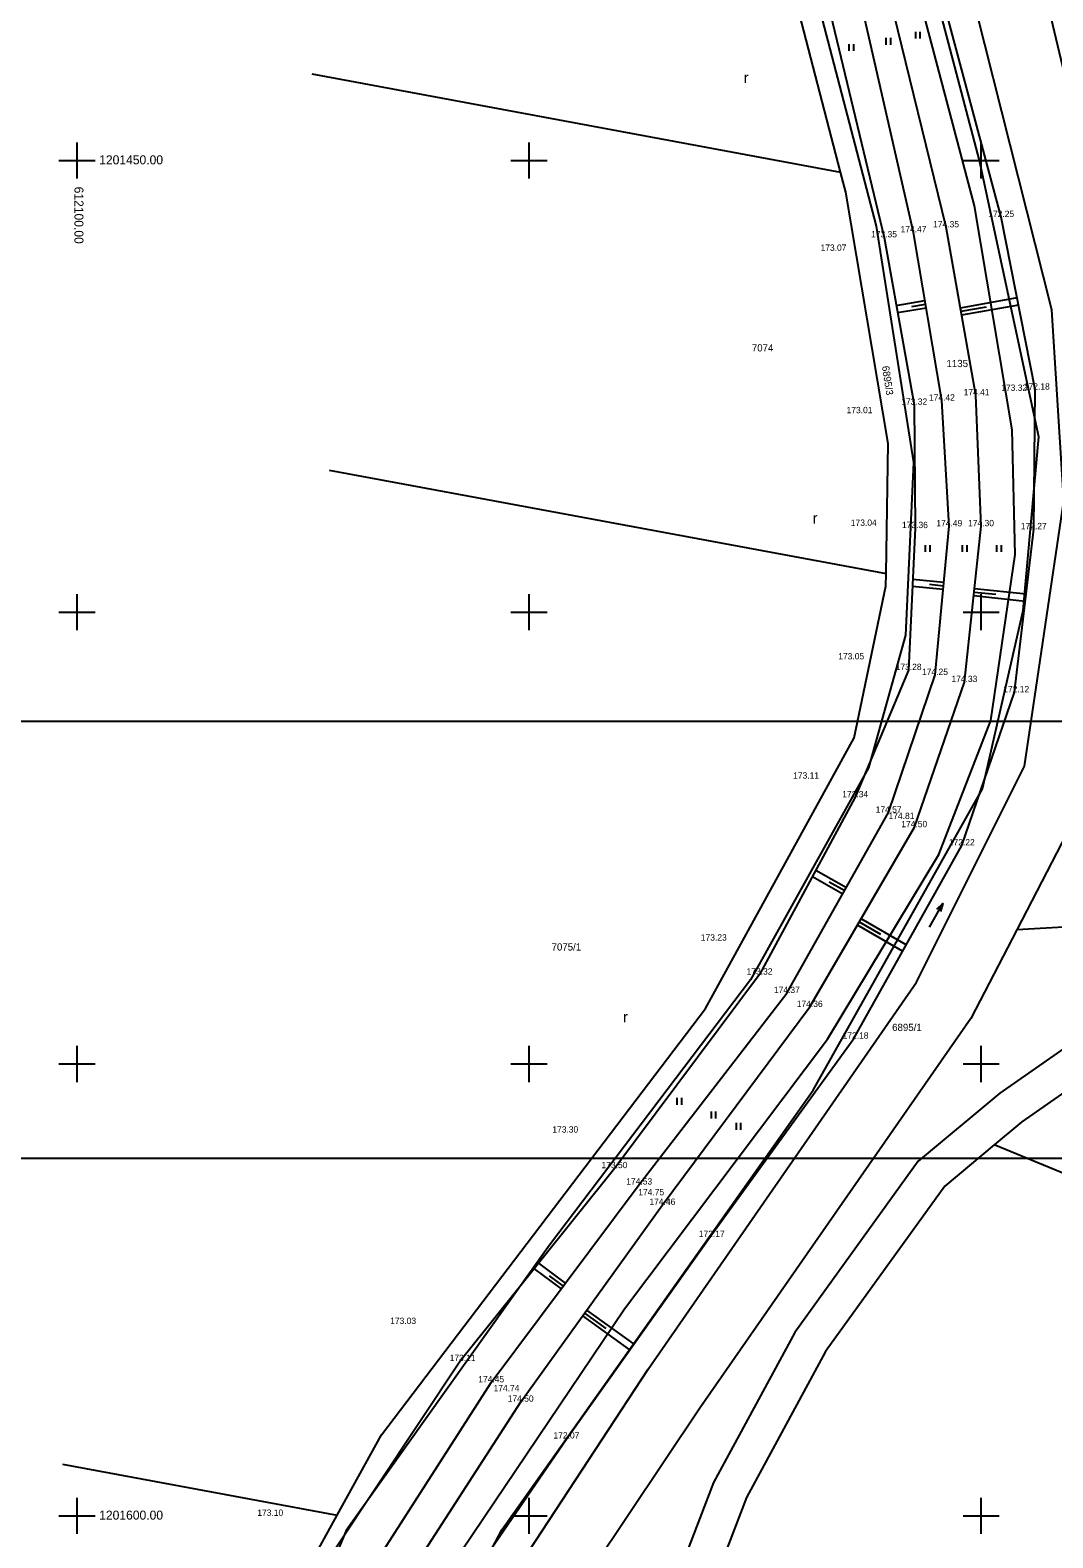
# Model space of a CAD drawing. Extents: x -612546 to -611926, y -1201932 to -1200444.
# Drawn here: x -612105.2 to -611992.1, y -1201602.4 to -1201435.6 of the extents above; entities that cross this region are included whole.
import ezdxf

# ---------------------------------------------------------------- set-up
doc = ezdxf.new("R2010")
doc.units = 0
for name, color, linetype in [('14 hrana pata svahu', 7, 'Continuous'), ('15 šrafy', 7, 'Continuous'), ('61 legenda křížky', 7, 'Continuous'), ('Hranice parcel', 7, 'Continuous'), ('Parcelní čísla', 7, 'Continuous'), ('Vnitřní kresba', 7, 'Continuous'), ('Vrstva 36', 7, 'Continuous'), ('Vrstva 45', 7, 'Continuous'), ('Vrstva 63', 7, 'Continuous'), ('výška bodu', 7, 'Continuous')]:
    doc.layers.add(name, color=color, linetype=linetype)

msp = doc.modelspace()

# ---------------------------------------------------------------- linework, layer by layer
at = {"layer": '14 hrana pata svahu'}
for points in [[(-612064.14, -1201607.91), (-612050.9, -1201587.38), (-612035.24, -1201565.59), (-612018.94, -1201543.69), (-612007.37, -1201523.79), (-612001.85, -1201507.73), (-611999.98, -1201490.48), (-612000.59, -1201475.99), (-612003.88, -1201457.4), (-612010.08, -1201431.88), (-612017.13, -1201405.07), (-612023.96, -1201380.26), (-612030.88, -1201354.05), (-612037.79, -1201327.9), (-612045.18, -1201301.85), (-612055.08, -1201267.97)], [(-612058.46, -1201609.91), (-612045.84, -1201591.45), (-612030, -1201569.15), (-612014.09, -1201547.19), (-612002.14, -1201525.81), (-611996.32, -1201508.86), (-611994.18, -1201490.81), (-611994.04, -1201475.36), (-611997.78, -1201456.26), (-612004.46, -1201431.28), (-612011.71, -1201404.48), (-612018.59, -1201378.49), (-612025.7, -1201352.72), (-612032.15, -1201326.28), (-612039.66, -1201300.7), (-612048.13, -1201268.75)], [(-612067.33, -1201605.71), (-612054.19, -1201585.24), (-612037.82, -1201563.34), (-612021.49, -1201542.15), (-612010.23, -1201522.18), (-612005.1, -1201506.94), (-612003.52, -1201490.49), (-612004.34, -1201476.58), (-612007.48, -1201457.96), (-612013.23, -1201432.72), (-612020.3, -1201406.08), (-612027.21, -1201381.29), (-612034.3, -1201355.08), (-612041.2, -1201328.91), (-612048.01, -1201302.49), (-612056.96, -1201270.5)], [(-612072.85, -1201271.87), (-612059.61, -1201273.55), (-612051.46, -1201303.54), (-612044.5, -1201329.67), (-612037.67, -1201355.97), (-612030.48, -1201382.34), (-612024.02, -1201407.2), (-612016.67, -1201433.81), (-612010.74, -1201458.51), (-612007.4, -1201477.04), (-612007.3, -1201490.69), (-612008.02, -1201506.4), (-612013.93, -1201520.48), (-612024.51, -1201540.1), (-612040.53, -1201561.53), (-612057.63, -1201582.88), (-612071.39, -1201603.6)]]:
    msp.add_lwpolyline(points, dxfattribs=at)
at = {"layer": '15 šrafy'}
for p, q in [((-612009.38, -1201466.04), (-612006.21, -1201465.51)), ((-612007.67, -1201466.16), (-612006.14, -1201465.9)), ((-611996.03, -1201465.22), (-612002.3, -1201466.33)), ((-612009.24, -1201466.83), (-612006.07, -1201466.3)), ((-611999.43, -1201466.23), (-612002.23, -1201466.73)), ((-611995.87, -1201466.01), (-612002.16, -1201467.12)), ((-612007.6, -1201497.13), (-612004.19, -1201497.46)), ((-612007.56, -1201496.33), (-612004.11, -1201496.66)), ((-612005.71, -1201496.91), (-612004.15, -1201497.06)), ((-611995.03, -1201498.01), (-612000.73, -1201497.4)), ((-611995.13, -1201498.81), (-612000.82, -1201498.19)), ((-611998.38, -1201498.05), (-612000.77, -1201497.8)), ((-612018.66, -1201529.25), (-612015.29, -1201531.15)), ((-612018.28, -1201528.55), (-612014.9, -1201530.46)), ((-612016.8, -1201529.84), (-612015.09, -1201530.81)), ((-612011.09, -1201535.67), (-612013.47, -1201534.29)), ((-612008.3, -1201536.83), (-612013.27, -1201533.94)), ((-612008.69, -1201537.53), (-612013.67, -1201534.63)), ((-612049.45, -1201572.67), (-612046.46, -1201574.9)), ((-612048.95, -1201572.05), (-612045.99, -1201574.26)), ((-612047.76, -1201573.44), (-612046.22, -1201574.58)), ((-612041.47, -1201579.26), (-612043.84, -1201577.56)), ((-612038.4, -1201580.97), (-612043.61, -1201577.23)), ((-612038.86, -1201581.63), (-612044.07, -1201577.88))]:
    msp.add_line(p, q, dxfattribs=at)
at = {"layer": '61 legenda křížky'}
for p, q in [((-612100, -1201452), (-612100, -1201448)), ((-612050, -1201452), (-612050, -1201448)), ((-612000, -1201452), (-612000, -1201448)), ((-612102, -1201450), (-612098, -1201450)), ((-612052, -1201450), (-612048, -1201450)), ((-612002, -1201450), (-611998, -1201450)), ((-612100, -1201502), (-612100, -1201498)), ((-612050, -1201502), (-612050, -1201498)), ((-612000, -1201502), (-612000, -1201498)), ((-612102, -1201500), (-612098, -1201500)), ((-612052, -1201500), (-612048, -1201500)), ((-612002, -1201500), (-611998, -1201500)), ((-612100, -1201552), (-612100, -1201548)), ((-612050, -1201552), (-612050, -1201548)), ((-612000, -1201552), (-612000, -1201548)), ((-612102, -1201550), (-612098, -1201550)), ((-612052, -1201550), (-612048, -1201550)), ((-612002, -1201550), (-611998, -1201550)), ((-612100, -1201602), (-612100, -1201598)), ((-612050, -1201602), (-612050, -1201598)), ((-612000, -1201602), (-612000, -1201598)), ((-612102, -1201600), (-612098, -1201600)), ((-612052, -1201600), (-612048, -1201600)), ((-612002, -1201600), (-611998, -1201600))]:
    msp.add_line(p, q, dxfattribs=at)
at = {"layer": 'Hranice parcel'}
for p, q in [((-612015.54, -1201451.28), (-612029.85, -1201396.29)), ((-611969.89, -1201533.65), (-611996.06, -1201535.15)), ((-611949.12, -1201579.28), (-611998.56, -1201558.96))]:
    msp.add_line(p, q, dxfattribs=at)
for points in [[(-612177.46, -1201854.09), (-612171.97, -1201847.65), (-612125.97, -1201786.38), (-612109.19, -1201764.04), (-612092.57, -1201737.14), (-612080.39, -1201714.9), (-612074.78, -1201703.41), (-612071.98, -1201691.65), (-612072.2, -1201658.35), (-612070, -1201637.27), (-612065.73, -1201619.85), (-612059.82, -1201607.37), (-612039.46, -1201577.1), (-612017, -1201547.24), (-612004.68, -1201526.81), (-611998.92, -1201511.99), (-611996.24, -1201493.62), (-611996.58, -1201479.8), (-612000.74, -1201455.02), (-612027.1, -1201355.18), (-612050.25, -1201267.11)], [(-612060.22, -1201274.37), (-612037.81, -1201356.84), (-612011.62, -1201457.28), (-612007.48, -1201483.41), (-612008.37, -1201502.54), (-612012.46, -1201517.21), (-612025.5, -1201540.7), (-612047.75, -1201570.04), (-612070.24, -1201601.65), (-612078.31, -1201621), (-612081.97, -1201637.65), (-612083.96, -1201662.29), (-612084.12, -1201685.12), (-612084.75, -1201695.31), (-612087.47, -1201703.35), (-612103.05, -1201731.95), (-612118.98, -1201757.79), (-612136.57, -1201780.34), (-612179.16, -1201837.25), (-612189.22, -1201833.81)], [(-612009.76, -1201369.19), (-611997.24, -1201413.36), (-611984.77, -1201465.78), (-611983.62, -1201488.16), (-611987.79, -1201519.18), (-611996.06, -1201535.15)], [(-612074.03, -1201440.4), (-612015.54, -1201451.28)], [(-612010.52, -1201495.71), (-612010.29, -1201481.32), (-612014.96, -1201453.49), (-612015.54, -1201451.28)], [(-611964.05, -1201475.97), (-611960.2, -1201490.55), (-611957.25, -1201508.03), (-611957.35, -1201519.46), (-611960.34, -1201531.68), (-611967.57, -1201536.91), (-611995.49, -1201556.41), (-611998.56, -1201558.96)], [(-612072.1, -1201484.26), (-612010.52, -1201495.71)], [(-612071.21, -1201599.94), (-612066.31, -1201591.05), (-612030.5, -1201543.86), (-612014.06, -1201513.9), (-612010.54, -1201497.12), (-612010.52, -1201495.71)], [(-611969.89, -1201533.65), (-611997.92, -1201553.23), (-612006.98, -1201560.76), (-612020.6, -1201579.7), (-612029.6, -1201596.32), (-612036.2, -1201613.55), (-612042.99, -1201636.89), (-612045.15, -1201648.68)], [(-611996.06, -1201535.15), (-612001.15, -1201544.98), (-612031.12, -1201588.08), (-612050.83, -1201617.6), (-612058.05, -1201640.39)], [(-611998.56, -1201558.96), (-612004.03, -1201563.51), (-612017.2, -1201581.83), (-612025.96, -1201597.99), (-612032.41, -1201614.83), (-612039.09, -1201637.81), (-612039.19, -1201638.35)], [(-612101.6, -1201594.29), (-612071.21, -1201599.94)], [(-612086.09, -1201665.74), (-612083.97, -1201635.12), (-612078.56, -1201613.28), (-612071.21, -1201599.94)]]:
    msp.add_lwpolyline(points, dxfattribs=at)
at = {"layer": 'Vnitřní kresba'}
for points in [[(-612170.38, -1201848.81), (-612152.03, -1201823.55), (-612114.84, -1201773.75), (-612096.57, -1201746.92), (-612078.95, -1201716.04), (-612070.37, -1201697.01), (-612068.25, -1201638.15), (-612062.56, -1201619.7), (-612053.03, -1201601.55), (-612018.56, -1201552.89), (-611999.85, -1201519.56), (-611995.35, -1201499.82), (-611993.63, -1201480.57), (-612000.19, -1201450.02), (-612024.45, -1201357.81), (-612050.25, -1201267.11)], [(-612167.45, -1201850.95), (-612159.31, -1201839.87), (-612135.2, -1201807.83), (-612099.97, -1201758.55), (-612082.71, -1201730.21), (-612068.43, -1201702.85), (-612066.16, -1201687.46), (-612066.16, -1201656.85), (-612064.63, -1201639.3), (-612057.32, -1201615.06), (-612036.83, -1201583.77), (-612007.13, -1201540.95), (-611995.21, -1201517.05), (-611990.85, -1201487.68), (-611992.18, -1201466.53), (-612005.11, -1201415.22), (-612025.88, -1201339.7), (-612042.61, -1201277.13), (-612043.67, -1201266.17)]]:
    msp.add_lwpolyline(points, dxfattribs=at)
at = {"layer": 'Vrstva 36'}
for p, q in [((-612007.23, -1201436.51), (-612007.23, -1201435.76)), ((-612006.73, -1201436.51), (-612006.73, -1201435.76)), ((-612014.58, -1201437.86), (-612014.58, -1201437.11)), ((-612014.08, -1201437.86), (-612014.08, -1201437.11)), ((-612010.5, -1201437.19), (-612010.5, -1201436.44)), ((-612010, -1201437.19), (-612010, -1201436.44)), ((-612006.14, -1201493.31), (-612006.14, -1201492.56)), ((-612005.64, -1201493.31), (-612005.64, -1201492.56)), ((-612002.06, -1201493.31), (-612002.06, -1201492.56)), ((-612001.56, -1201493.31), (-612001.56, -1201492.56)), ((-611998.26, -1201493.31), (-611998.26, -1201492.56)), ((-611997.76, -1201493.31), (-611997.76, -1201492.56)), ((-612033.62, -1201554.51), (-612033.62, -1201553.76)), ((-612033.12, -1201554.51), (-612033.12, -1201553.76)), ((-612029.84, -1201556.02), (-612029.84, -1201555.27)), ((-612029.34, -1201556.02), (-612029.34, -1201555.27)), ((-612027.06, -1201557.28), (-612027.06, -1201556.53)), ((-612026.56, -1201557.28), (-612026.56, -1201556.53))]:
    msp.add_line(p, q, dxfattribs=at)
at = {"layer": 'Vrstva 45'}
msp.add_line((-612005.72, -1201534.85), (-612004.25, -1201532.23), dxfattribs=at)
msp.add_lwpolyline([(-612004.88, -1201532.88), (-612004.25, -1201532.23), (-612004.48, -1201533.11)], dxfattribs=at)
at = {"layer": 'Vrstva 63'}
for p, q in [((-612244.2, -1201512.06), (-611947.2, -1201512.06)), ((-611925.92, -1201560.45), (-612222.92, -1201560.45))]:
    msp.add_line(p, q, dxfattribs=at)

# ---------------------------------------------------------------- texts
at = {"layer": '61 legenda křížky'}
for s, p in [('1201450.00', (-612097.55, -1201450.43)), ('1201600.00', (-612097.55, -1201600.43))]:
    msp.add_text(s, height=1, dxfattribs=at).set_placement(p)
msp.add_text('612100.00', height=1, rotation=270, dxfattribs=at).set_placement((-612100.29, -1201452.9))
at = {"layer": 'Parcelní čísla'}
for s, p in [('7074', (-612025.36, -1201471.14)), ('1135', (-612003.83, -1201472.87)), ('7075/1', (-612047.51, -1201537.44)), ('6895/1', (-612009.84, -1201546.35))]:
    msp.add_text(s, height=0.8, dxfattribs=at).set_placement(p)
msp.add_text('6895/3', height=0.8, rotation=278.5677, dxfattribs=at).set_placement((-612010.97, -1201472.79))
at = {"layer": 'Vrstva 36'}
for p in [(-612026.26, -1201441.44), (-612018.63, -1201490.19), (-612039.6, -1201545.4)]:
    msp.add_text('r', height=1.2, dxfattribs=at).set_placement(p)
at = {"layer": 'výška bodu'}
for s, p in [('172.25', (-611999.21, -1201456.26)), ('174.47', (-612008.91, -1201457.96)), ('174.35', (-612005.31, -1201457.4)), ('173.35', (-612012.17, -1201458.51)), ('173.07', (-612017.76, -1201460)), ('174.42', (-612005.77, -1201476.58)), ('174.41', (-612001.93, -1201475.99)), ('173.32', (-611997.77, -1201475.5)), ('172.18', (-611995.27, -1201475.36)), ('173.01', (-612014.88, -1201477.97)), ('173.32', (-612008.83, -1201477.04)), ('173.04', (-612014.41, -1201490.44)), ('173.36', (-612008.75, -1201490.69)), ('174.49', (-612004.95, -1201490.49)), ('174.30', (-612001.44, -1201490.48)), ('172.27', (-611995.61, -1201490.81)), ('173.05', (-612015.8, -1201505.22)), ('173.28', (-612009.45, -1201506.4)), ('174.25', (-612006.53, -1201506.94)), ('174.33', (-612003.28, -1201507.73)), ('172.12', (-611997.55, -1201508.86)), ('173.11', (-612020.79, -1201518.41)), ('173.34', (-612015.36, -1201520.48)), ('174.57', (-612011.66, -1201522.18)), ('174.81', (-612010.24, -1201522.89)), ('174.50', (-612008.83, -1201523.79)), ('172.22', (-612003.57, -1201525.81)), ('173.23', (-612031, -1201536.34)), ('173.32', (-612025.94, -1201540.1)), ('174.37', (-612022.92, -1201542.15)), ('174.36', (-612020.39, -1201543.69)), ('172.18', (-612015.32, -1201547.19)), ('173.30', (-612047.43, -1201557.59)), ('173.50', (-612041.99, -1201561.53)), ('174.53', (-612039.25, -1201563.34)), ('174.75', (-612037.92, -1201564.53)), ('174.46', (-612036.69, -1201565.59)), ('172.17', (-612031.23, -1201569.15)), ('173.03', (-612065.36, -1201578.77)), ('173.11', (-612058.78, -1201582.88)), ('174.45', (-612055.62, -1201585.24)), ('174.74', (-612053.93, -1201586.22)), ('174.50', (-612052.36, -1201587.38)), ('172.07', (-612047.3, -1201591.45)), ('173.10', (-612080.06, -1201600.01))]:
    msp.add_text(s, height=0.7, dxfattribs=at).set_placement(p)

doc.saveas('drawing.dxf')
